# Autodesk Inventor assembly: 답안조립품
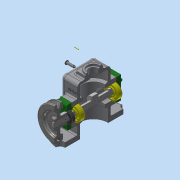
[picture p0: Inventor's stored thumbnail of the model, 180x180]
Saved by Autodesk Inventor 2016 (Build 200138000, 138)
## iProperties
Created: 2018-07
Part Number: 답안조립품
Material: 일반
Document SubType Name: Assembly
Designer: 2-PC02
Author: 2-PC02
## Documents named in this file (11)
- C:\Users\2-PC02\Desktop\480708V1008\480708V1008\답안조립품.iam
- C:\Users\2-PC02\Desktop\480708V1008\480708V1008\본체.ipt
- C:\Users\2-PC02\Desktop\480708V1008\뒤커버.ipt
- C:\Users\2-PC02\Desktop\480708V1008\편심축.ipt
- C:\Users\2-PC02\Desktop\480708V1008\베어링 12x32x10.ipt
- C:\Users\2-PC02\Desktop\480708V1008\앞커버.ipt
- C:\Users\2-PC02\Desktop\480708V1008\오일 실 12 25 7.ipt
- C:\Users\2-PC02\Desktop\480708V1008\V벨트풀리.ipt
- C:\Users\2-PC02\Desktop\480708V1008\키 4x4x10.ipt
- C:\Users\2-PC02\Desktop\480708V1008\핀 5x18.ipt
- C:\Users\2-PC02\Desktop\480708V1008\고정핀 1.2x8.ipt
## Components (3 placed, 3 different names)
1. V벨트풀리:1
2. 핀 5x18:1
3. 고정핀 1.2x8:1
